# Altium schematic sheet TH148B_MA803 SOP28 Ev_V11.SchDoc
size 279 x 193 mm; PageSetup: Record=PageOptions|CenterHorizontal=True|CenterVertical=True|PrintScale=1.05|XCorrection=1.00|YCorrection=1.00|PrintKind=0|BorderSize=5000000|LeftOffset=0|BottomOffset=0|Orientation=2|PaperLength=1000|PaperWidth=1000|Scale=100|PaperSource=7|PrintQuality=-4|MediaType=1|DitherType=10|PaperKind=A4|PrintScaleMode=1
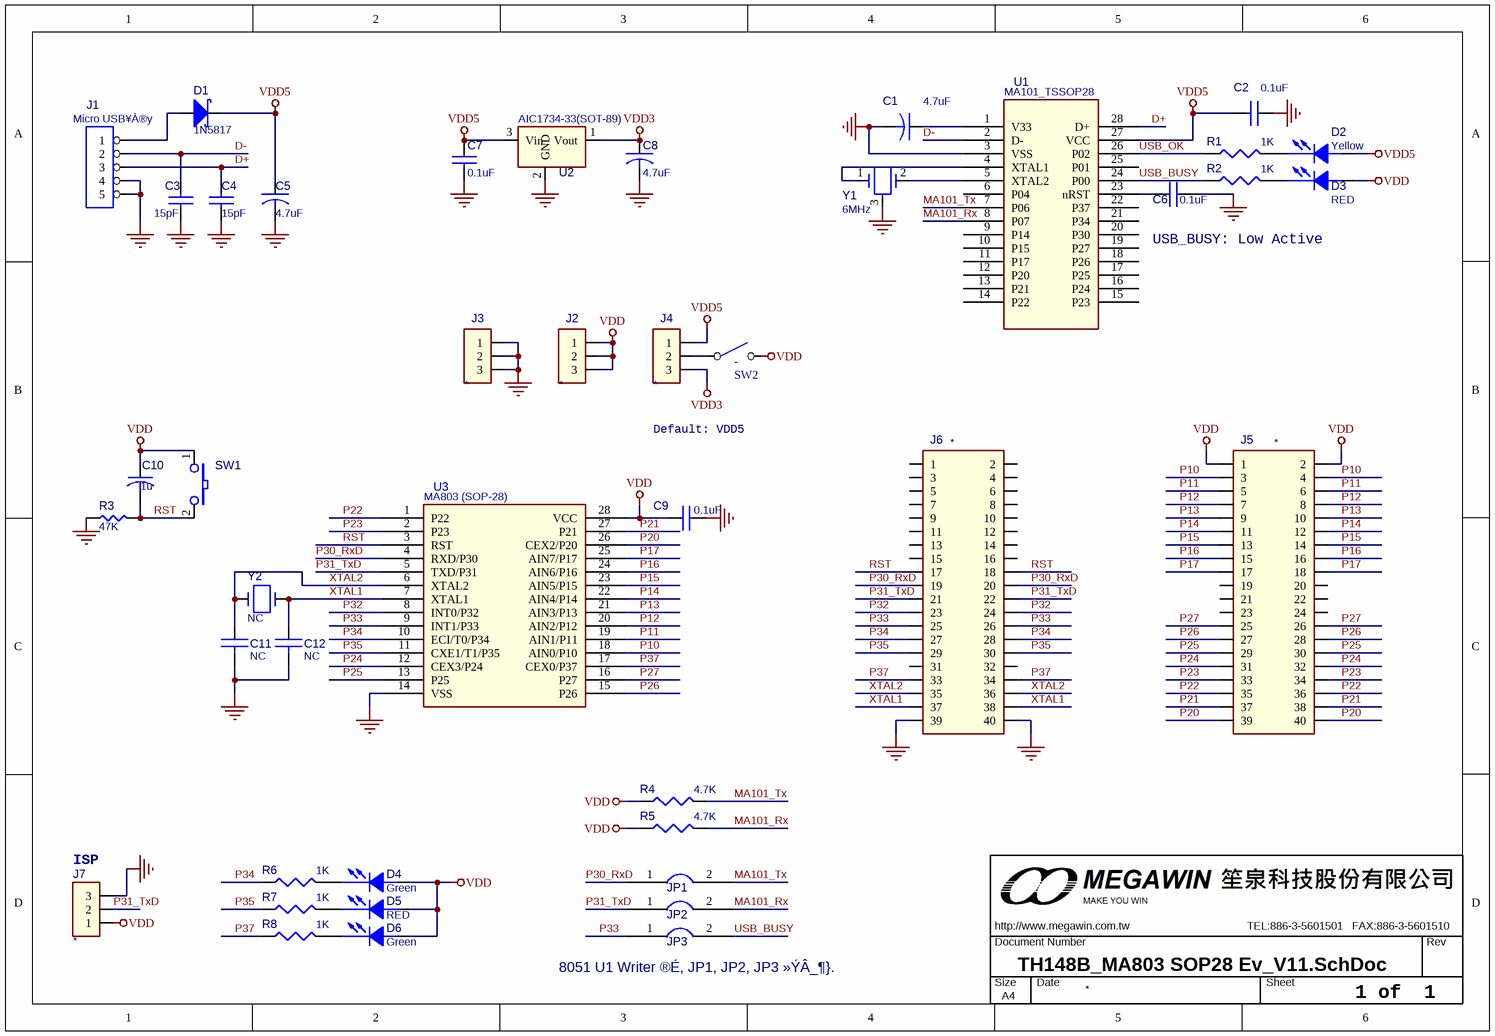
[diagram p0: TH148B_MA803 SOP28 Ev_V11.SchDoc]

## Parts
C1  4.7uF  [0805C]
C2  0.1uF  [0805C]
C3  15pF  [0805C]
C4  15pF  [0805C]
C5  4.7uF  [1206C]
C6  0.1uF  [0805C]
C7  0.1uF  [0805C]
C8  4.7uF  [0805C]
C9  0.1uF  [0805C]
C10  1u  [0805C]
C11  NC  [0805C]
C12  NC  [0805C]
D1  1N5817  [D5817_SMD_1]
D2  Yellow  [0805D]
D3  RED  [0805D]
D4  Green  [0805D]
D5  RED  [0805D]
D6  Green  [0805D]
J1  Micro USB¥À®y  [JACK_USB_SMD290X220P065]
J2  *  [PS3P254]
J3  *  [PS3P254]
J4  *  [JUMP3_SMD]
J5  *  [PS20X2P254]
J6  *  [PS20X2P254]
J7  *  [PS3P254f_90]
JP1  JUMPER2  [PS2P254]  (value not drawn)
JP2  JUMPER2  [PS2P254]  (value not drawn)
JP3  JUMPER2  [PS2P254]  (value not drawn)
MW1  OrgAddr3: TEL:886-3-5601501   FAX:886-3-5601510  Page Size: A4  [MEGAWIN10_1]  (hidden comment: MW_A4_1)  (graphical)
R1  1K  [0805R]
R2  1K  [0805R]
R3  47K  [0805R]
R4  4.7K  [0805R]
R5  4.7K  [0805R]
R6  1K  [0805R]
R7  1K  [0805R]
R8  1K  [0805R]
SW1  SW TACT-SPST  [SW_T_2P]  (value not drawn)
SW2  -  [DIP2_SW]
U1  MA101_TSSOP28  [TSSOP28_170P065]
U2  AIC1734-33(SOT-89)  [SOT89]
U3  MA803 (SOP-28)  [SO28_300P127]
Y1  6MHz  [X3P]
Y2  NC  [X49U]

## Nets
GND_POWER: C1.2 C2.1 C3.2 C4.2 C5.2 C6.1 C7.2 C8.2 C9.2 C11.2 C12.2 J1.4 J1.5 J3.1 J3.2 J3.3 J6.39 J6.40 J7.3 R3.1 U1.3(VSS) U2.2(GND) U3.14(VSS) Y1.3
VDD: C9.1 C10.1(POS) D3.1(ANODE) D4.1(ANODE) D5.1(ANODE) D6.1(ANODE) J2.1 J2.2 J2.3 J5.1 J5.2 J7.1 R4.1 R5.1 SW1.1 SW2.2(NO) U3.28(VCC)
VDD3: C8.1 J4.3 U2.1(Vout)
VDD5: C2.2 C5.1 C7.1 D1.2(K) D2.1(ANODE) J4.1 U1.27(VCC) U2.3(Vin)
D+: C4.1 J1.3 U1.28(D+)
D-: C3.1 J1.2 U1.2(D-)
MA101_Rx: JP2.2 R5.2 U1.8(P07)
MA101_Tx: JP1.2 R4.2 U1.7(P06)
P10: J5.3 J5.4 U3.18(AIN0/P10)
P11: J5.5 J5.6 U3.19(AIN1/P11)
P12: J5.7 J5.8 U3.20(AIN2/P12)
P13: J5.9 J5.10 U3.21(AIN3/P13)
P14: J5.11 J5.12 U3.22(AIN4/P14)
P15: J5.13 J5.14 U3.23(AIN5/P15)
P16: J5.15 J5.16 U3.24(AIN6/P16)
P17: J5.17 J5.18 U3.25(AIN7/P17)
P20: J5.39 J5.40 U3.26(CEX2/P20)
P21: J5.37 J5.38 U3.27(P21)
P22: J5.35 J5.36 U3.1(P22)
P23: J5.33 J5.34 U3.2(P23)
P24: J5.31 J5.32 U3.12(CEX3/P24)
P25: J5.29 J5.30 U3.13(P25)
P26: J5.27 J5.28 U3.15(P26)
P27: J5.25 J5.26 U3.16(P27)
P30_RxD: J6.19 J6.20 JP1.1 U3.4(RXD/P30)
P31_TxD: J6.21 J6.22 J7.2 JP2.1 U3.5(TXD/P31)
P32: J6.23 J6.24 U3.8(INT0/P32)
P33: J6.25 J6.26 JP3.1 U3.9(INT1/P33)
P34: J6.27 J6.28 R6.1 U3.10(ECI/T0/P34)
P35: J6.29 J6.30 R7.1 U3.11(CXE1/T1/P35)
P37: J6.33 J6.34 R8.1 U3.17(CEX0/P37)
RST: C10.2(NEG) J6.17 J6.18 R3.2 SW1.2 U3.3(RST)
USB_BUSY: JP3.2 R2.1 U1.24(P00)
USB_OK: R1.1 U1.26(P02)
XTAL1: C12.1 J6.37 J6.38 U3.7(XTAL1) Y2.2
XTAL2: C11.1 J6.35 J6.36 U3.6(XTAL2) Y2.1
NetC1_1: C1.1 U1.1(V33)
NetC6_2: C6.2 U1.23(nRST)
NetD1_1: D1.1(A) J1.1
NetD2_2: D2.2(CATHODE) R1.2
NetD3_2: D3.2(CATHODE) R2.2
NetD4_2: D4.2(CATHODE) R6.2
NetD5_2: D5.2(CATHODE) R7.2
NetD6_2: D6.2(CATHODE) R8.2
NetJ4_2: J4.2 SW2.1(COMMON)
NetU1_4: U1.4(XTAL1) Y1.1
NetU1_5: U1.5(XTAL2) Y1.2

Not connected (* = marked no-connect by the designer): J5 19 20 21 22 23 24; J6 1 2 3 4 5 6 7 8 9 10 11 12 13 14 15 16 31 32; U1 6(P04) 9(P14) 10(P15) 11(P17) 12(P20) 13(P21) 14(P22) 15(P23) 16(P24) 17(P25) 18(P26) 19(P27) 20(P30) 21(P34) 22(P37) 25(P01)

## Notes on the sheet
- USB_BUSY: Low Active
- Default: VDD5
- (near J7) ISP
- (near JP3) 8051 U1 Writer ®É, JP1, JP2, JP3 »ÝÂ_¶}.
- 1 of  1

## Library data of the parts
C1 C5 C8 = CAP
C2-C4 C6 C7 C9 = CAP NP
C10 = C
C11 C12 = C NP
D1 = DIODE_ZD: Schottky Diode
D2-D6 = LED
J1 = CON5: Connector
J2-J4 J7 = CON3
J5 J6 = CON40A
R1 R2 R4-R8 = R_Dup1
R3 = R
SW2 = SW-2
U2 = AIC1734-33(SOT-89)_0
U3 = MPC82L54(TSSOP28)
Y1 = CRYSTAL_RC
Y2 = CRYSTAL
